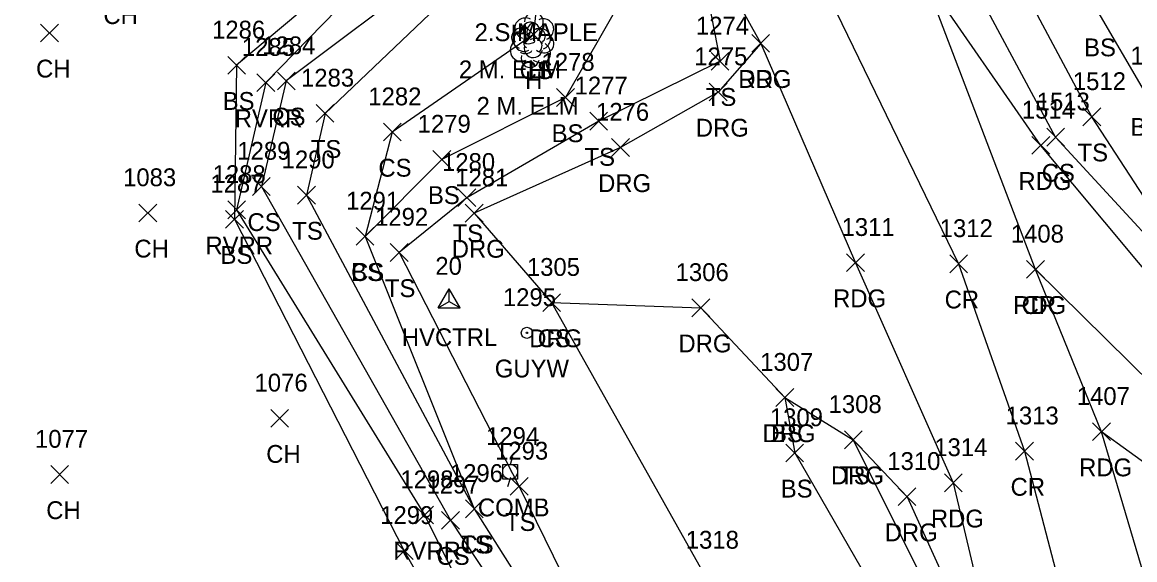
# Model space of a CAD drawing. Extents: x 1469310 to 1475157, y 493997 to 498873.
# Drawn here: x 1469498.4 to 1469623, y 498476.8 to 498537.1 of the extents above; entities that cross this region are included whole.
import ezdxf

# ---------------------------------------------------------------- set-up
doc = ezdxf.new("R2010")
doc.units = 0
for name, color, linetype in [('C_A', 7, 'Continuous'), ('C_I', 7, 'Continuous'), ('CPSM', 7, 'Continuous'), ('L_A', 7, 'Continuous'), ('L_C', 7, 'Continuous'), ('L_I', 7, 'Continuous'), ('L_TIC', 7, 'Continuous'), ('LAWE', 7, 'Continuous'), ('LELB', 7, 'Continuous'), ('LTD', 7, 'Continuous'), ('P_A', 7, 'Continuous'), ('P_I', 7, 'Continuous'), ('P_TIC', 7, 'Continuous'), ('PEU', 7, 'Continuous'), ('PRC', 7, 'Continuous'), ('R_A', 7, 'Continuous'), ('R_I', 7, 'Continuous'), ('R_TIC', 7, 'Continuous'), ('RDG', 7, 'Continuous'), ('U_A', 7, 'Continuous'), ('U_I', 7, 'Continuous'), ('UP', 7, 'Continuous'), ('UPGW', 7, 'Continuous')]:
    doc.layers.add(name, color=color, linetype=linetype)

msp = doc.modelspace()

# ---------------------------------------------------------------- linework, layer by layer
at = {"layer": 'CPSM'}
for p, q in [((1469544.97, 498505), (1469546.22, 498507.16)), ((1469547.47, 498505), (1469546.22, 498507.16)), ((1469546.22, 498505.72), (1469546.22, 498507.16)), ((1469544.97, 498505), (1469546.22, 498505.72)), ((1469544.97, 498505), (1469547.47, 498505)), ((1469546.22, 498505.72), (1469546.22, 498505.72)), ((1469546.22, 498505.72), (1469547.47, 498505))]:
    msp.add_line(p, q, dxfattribs=at)
at = {"layer": 'L_TIC'}
for points in [[(1469500.44, 498534.85), (1469502.44, 498536.85)], [(1469502.44, 498534.85), (1469500.44, 498536.85)], [(1469554.67, 498534.67), (1469556.67, 498536.67)], [(1469556.67, 498534.67), (1469554.67, 498536.67)], [(1469575.57, 498531.67), (1469577.57, 498533.67)], [(1469577.57, 498531.67), (1469575.57, 498533.67)], [(1469521.4, 498531.22), (1469523.4, 498533.22)], [(1469523.4, 498531.22), (1469521.4, 498533.22)], [(1469524.68, 498529.28), (1469526.68, 498531.28)], [(1469526.68, 498529.28), (1469524.68, 498531.28)], [(1469526.97, 498529.46), (1469528.97, 498531.46)], [(1469528.97, 498529.46), (1469526.97, 498531.46)], [(1469558.26, 498527.6), (1469560.26, 498529.6)], [(1469560.26, 498527.6), (1469558.26, 498529.6)], [(1469531.31, 498525.83), (1469533.31, 498527.83)], [(1469533.31, 498525.83), (1469531.31, 498527.83)], [(1469617.23, 498525.44), (1469619.23, 498527.44)], [(1469619.23, 498525.44), (1469617.23, 498527.44)], [(1469561.98, 498524.95), (1469563.98, 498526.95)], [(1469563.98, 498524.95), (1469561.98, 498526.95)], [(1469538.85, 498523.73), (1469540.85, 498525.73)], [(1469540.85, 498523.73), (1469538.85, 498525.73)], [(1469613.18, 498523.16), (1469615.18, 498525.16)], [(1469615.18, 498523.16), (1469613.18, 498525.16)], [(1469544.4, 498520.66), (1469546.4, 498522.66)], [(1469546.4, 498520.66), (1469544.4, 498522.66)], [(1469524.18, 498517.63), (1469526.18, 498519.63)], [(1469526.18, 498517.63), (1469524.18, 498519.63)], [(1469529.23, 498516.66), (1469531.23, 498518.66)], [(1469531.23, 498516.66), (1469529.23, 498518.66)], [(1469547.2, 498516.37), (1469549.2, 498518.37)], [(1469549.2, 498516.37), (1469547.2, 498518.37)], [(1469511.46, 498514.66), (1469513.46, 498516.66)], [(1469513.46, 498514.66), (1469511.46, 498516.66)], [(1469521.16, 498513.95), (1469523.16, 498515.95)], [(1469523.16, 498513.95), (1469521.16, 498515.95)], [(1469521.4, 498515.01), (1469523.4, 498517.01)], [(1469523.4, 498515.01), (1469521.4, 498517.01)], [(1469535.79, 498512.03), (1469537.79, 498514.03)], [(1469537.79, 498512.03), (1469535.79, 498514.03)], [(1469535.79, 498512.03), (1469537.79, 498514.03)], [(1469537.79, 498512.03), (1469535.79, 498514.03)], [(1469539.61, 498510.22), (1469541.61, 498512.22)], [(1469541.61, 498510.22), (1469539.61, 498512.22)], [(1469556.7, 498504.6), (1469558.7, 498506.6)], [(1469558.7, 498504.6), (1469556.7, 498506.6)], [(1469582.84, 498493.95), (1469584.84, 498495.95)], [(1469584.84, 498493.95), (1469582.84, 498495.95)], [(1469526.23, 498491.63), (1469528.23, 498493.63)], [(1469528.23, 498491.63), (1469526.23, 498493.63)], [(1469590.51, 498489.22), (1469592.51, 498491.22)], [(1469592.51, 498489.22), (1469590.51, 498491.22)], [(1469583.94, 498487.74), (1469585.94, 498489.74)], [(1469585.94, 498487.74), (1469583.94, 498489.74)], [(1469501.58, 498485.32), (1469503.58, 498487.32)], [(1469503.58, 498485.32), (1469501.58, 498487.32)], [(1469553.07, 498483.99), (1469555.07, 498485.99)], [(1469555.07, 498483.99), (1469553.07, 498485.99)], [(1469548.04, 498481.48), (1469550.04, 498483.48)], [(1469550.04, 498481.48), (1469548.04, 498483.48)], [(1469548.04, 498481.48), (1469550.04, 498483.48)], [(1469550.04, 498481.48), (1469548.04, 498483.48)], [(1469542.45, 498480.78), (1469544.45, 498482.78)], [(1469544.45, 498480.78), (1469542.45, 498482.78)], [(1469545.36, 498480.19), (1469547.36, 498482.19)], [(1469547.36, 498480.19), (1469545.36, 498482.19)], [(1469540.19, 498476.77), (1469542.19, 498478.77)], [(1469542.19, 498476.77), (1469540.19, 498478.77)]]:
    msp.add_lwpolyline(points, dxfattribs=at)
at = {"layer": 'LAWE'}
msp.add_lwpolyline([(1469541.73, 498555.03), (1469545.19, 498552.67), (1469541.67, 498546.71), (1469525.68, 498530.28), (1469522.4, 498516.01), (1469543.45, 498481.78), (1469558.18, 498452.24), (1469573.2, 498427.49), (1469574.96, 498400.53), (1469574.71, 498375.54), (1469575.48, 498352.31), (1469575.94, 498330.63)], dxfattribs=at)
at = {"layer": 'LELB'}
for points in [[(1469416.82, 498734.31), (1469446.33, 498703.1), (1469470.89, 498677.65), (1469509.28, 498636.71), (1469524.42, 498615.8), (1469544.37, 498592.02), (1469564.88, 498563.16), (1469574.6, 498542.86), (1469576.57, 498532.67), (1469562.98, 498525.95), (1469548.2, 498517.37), (1469540.61, 498511.22), (1469554.07, 498484.99), (1469566.51, 498459.59)], [(1469413.42, 498730.94), (1469442.52, 498698.7), (1469468.45, 498674.77), (1469500.53, 498635.82), (1469519, 498614.53), (1469533.17, 498594.86), (1469544.52, 498587.12), (1469562.89, 498554.7), (1469567.79, 498543.52), (1469559.26, 498528.6), (1469545.4, 498521.66), (1469536.79, 498513.03)], [(1469428.53, 498658.9), (1469433.57, 498648.51), (1469459.29, 498614.44), (1469478.33, 498589.06), (1469483.97, 498576.63), (1469489.34, 498572.76), (1469492.49, 498571.98), (1469507.99, 498581.09), (1469520.42, 498585.29), (1469534.63, 498584.29), (1469538.32, 498574.02), (1469547.83, 498560.42), (1469557.44, 498552.67), (1469555.67, 498535.67), (1469539.85, 498524.73), (1469536.79, 498513.03), (1469549.04, 498482.48), (1469564.46, 498458.05), (1469576.5, 498438.75), (1469578.88, 498431.59)], [(1469540.58, 498559.41), (1469542.48, 498560.06), (1469547.83, 498560.42), (1469552.04, 498551.8), (1469550.24, 498543.93), (1469532.31, 498526.83), (1469530.23, 498517.66), (1469549.04, 498482.48)], [(1469633.1, 498503.6), (1469614.18, 498524.16), (1469603.37, 498544.32), (1469596.34, 498559.71)], [(1469542.74, 498553.27), (1469541.61, 498548.4), (1469522.4, 498532.22), (1469522.16, 498514.95), (1469541.19, 498477.77), (1469556.44, 498450.64), (1469569.24, 498427.49), (1469571.75, 498396.28), (1469571.57, 498374.72), (1469573.65, 498352.84), (1469573.82, 498331.47)], [(1469788.82, 498394.72), (1469772.49, 498406.1), (1469747.63, 498424.65), (1469713.94, 498449.33), (1469681.33, 498467.82), (1469654.97, 498486.97), (1469638.09, 498508.74), (1469624.13, 498529.31), (1469618.93, 498538.23), (1469619.74, 498548.83)], [(1469787.64, 498392.56), (1469771.33, 498404.28), (1469746.15, 498422.39), (1469712.15, 498445.44), (1469680.51, 498465.06), (1469652.75, 498484.35), (1469633.1, 498503.6), (1469618.23, 498526.44), (1469608.67, 498544.39), (1469612.83, 498546.46)], [(1469550.24, 498543.93), (1469544.51, 498542.94), (1469527.97, 498530.46), (1469525.18, 498518.63), (1469546.36, 498481.19), (1469563.05, 498455.92), (1469576.5, 498438.75)], [(1469557.7, 498505.6), (1469574.86, 498475), (1469581.06, 498460.66), (1469589.28, 498449.31), (1469594.14, 498440.51), (1469588.36, 498422.33), (1469583.12, 498414.68)], [(1469583.84, 498494.95), (1469584.94, 498488.74), (1469602.02, 498459.07), (1469610.17, 498437.24), (1469617.9, 498405.01), (1469618.1, 498399.47), (1469619.65, 498362.97), (1469614.57, 498335.86)], [(1469591.51, 498490.22), (1469607.36, 498458.33), (1469613.96, 498438.31), (1469620.12, 498405.06), (1469621.11, 498400.23), (1469624.57, 498362.54), (1469624.83, 498333.54)]]:
    msp.add_lwpolyline(points, dxfattribs=at)
at = {"layer": 'LTD'}
for p, q in [((1469555.3, 498534.56), (1469555.3, 498534.56)), ((1469555.3, 498534.56), (1469555.3, 498534.56)), ((1469555.67, 498535.67), (1469555.67, 498535.67)), ((1469555.67, 498535.67), (1469555.67, 498535.67))]:
    msp.add_line(p, q, dxfattribs=at)
for centre in [(1469555.35, 498536), (1469555.71, 498537.1)]:
    msp.add_arc(centre, 1.05, 335.5272, 180.9563, dxfattribs=at)
for centre, major_axis, ratio, start_param, end_param in [((1469554.88, 498536.33), (1.21, -0.51), 0.895232, 1.570796, 4.712389), ((1469555.46, 498536.12), (-0.208, -0.792), 0.645439, 3.141593, 6.283185), ((1469556.71, 498536.25), (-1.14, -0.48), 0.949671, 1.570796, 4.712389), ((1469554.51, 498535.23), (1.21, -0.51), 0.895232, 1.570796, 4.712389), ((1469554.58, 498534.96), (0.58, -1.04), 0.959034, 3.141593, 6.283185), ((1469555.1, 498535.02), (-0.208, -0.792), 0.645439, 3.141593, 6.283185), ((1469556.17, 498535.5), (-0.5, 0.667), 0.989748, 3.141593, 6.283185), ((1469556.35, 498535.15), (-1.14, -0.48), 0.949671, 1.570796, 4.712389), ((1469556.67, 498534.83), (-1.09, 0.79), 0.841452, 1.570796, 4.712389), ((1469554.22, 498533.85), (0.58, -1.04), 0.959034, 3.141593, 6.283185), ((1469555.21, 498534.92), (-0.625, -0.083), 0.423636, 0, 3.141593), ((1469555.8, 498534.4), (-0.5, 0.667), 0.989748, 3.141593, 6.283185), ((1469556.31, 498533.73), (-1.09, 0.79), 0.841452, 1.570796, 4.712389), ((1469555.31, 498533.06), (0.26, 1.06), 0.942809, 1.570796, 4.712389), ((1469554.85, 498533.81), (-0.625, -0.083), 0.423636, 0, 3.141593), ((1469555.67, 498534.17), (0.26, 1.06), 0.942809, 1.570796, 4.712389)]:
    msp.add_ellipse(centre, major_axis=major_axis, ratio=ratio, start_param=start_param, end_param=end_param, dxfattribs=at)
at = {"layer": 'P_TIC'}
for points in [[(1469580.13, 498533.68), (1469582.13, 498535.68)], [(1469582.13, 498533.68), (1469580.13, 498535.68)], [(1469611.52, 498522.24), (1469613.52, 498524.24)], [(1469613.52, 498522.24), (1469611.52, 498524.24)], [(1469590.75, 498509.08), (1469592.75, 498511.08)], [(1469592.75, 498509.08), (1469590.75, 498511.08)], [(1469602.31, 498508.95), (1469604.31, 498510.95)], [(1469604.31, 498508.95), (1469602.31, 498510.95)], [(1469610.93, 498508.33), (1469612.93, 498510.33)], [(1469612.93, 498508.33), (1469610.93, 498510.33)], [(1469610.93, 498508.33), (1469612.93, 498510.33)], [(1469612.93, 498508.33), (1469610.93, 498510.33)], [(1469618.32, 498490.12), (1469620.32, 498492.12)], [(1469620.32, 498490.12), (1469618.32, 498492.12)], [(1469609.7, 498487.94), (1469611.7, 498489.94)], [(1469611.7, 498487.94), (1469609.7, 498489.94)], [(1469601.71, 498484.38), (1469603.71, 498486.38)], [(1469603.71, 498484.38), (1469601.71, 498486.38)]]:
    msp.add_lwpolyline(points, dxfattribs=at)
at = {"layer": 'PEU'}
for points in [[(1469787.29, 498391.19), (1469770.79, 498403.19), (1469744.94, 498420.51), (1469711.23, 498443.77), (1469680.07, 498463.21), (1469651.58, 498483.41), (1469630.63, 498501.52), (1469612.52, 498523.24), (1469599.41, 498542.19), (1469591.57, 498556.6), (1469575.61, 498583.06), (1469557.31, 498607.49), (1469540.09, 498628.65), (1469536.24, 498634.99), (1469514.98, 498658.51), (1469490.83, 498684.27), (1469472.69, 498702.57), (1469444.89, 498732.16), (1469424.97, 498753.74), (1469411.28, 498767.74), (1469386.83, 498794.07), (1469360.47, 498820.44)], [(1469418.16, 498735.54), (1469447.91, 498704.22), (1469471.83, 498679.03), (1469509.9, 498637.99), (1469529.4, 498614.8), (1469545.14, 498594.13), (1469565.65, 498563.08), (1469576.41, 498543.24), (1469581.13, 498534.68), (1469591.75, 498510.08), (1469602.71, 498485.38), (1469609.03, 498458.44), (1469615.47, 498438.56), (1469621.98, 498404.81), (1469621.72, 498400.42), (1469625.38, 498362.57), (1469626.2, 498333.72)], [(1469637.73, 498433.09), (1469628.78, 498459.19), (1469619.32, 498491.12), (1469611.93, 498509.33), (1469599.41, 498542.19)]]:
    msp.add_lwpolyline(points, dxfattribs=at)
at = {"layer": 'PRC'}
for points in [[(1469423.49, 498741.59), (1469452.57, 498710.45), (1469477.96, 498685.46), (1469512.01, 498647.6), (1469532.7, 498623.32), (1469554.78, 498596.5), (1469570.66, 498571.79), (1469585.25, 498547.18), (1469603.31, 498509.95), (1469610.7, 498488.94), (1469623.7, 498439.14), (1469630.72, 498407.83), (1469631.04, 498401.91), (1469634.46, 498363.9), (1469634.52, 498333.31)], [(1469611.93, 498509.33), (1469635.59, 498485.96), (1469656.26, 498471.44), (1469676.23, 498459.15), (1469677.31, 498457.92), (1469704.76, 498441.38), (1469729.86, 498424.4), (1469757.53, 498405.58), (1469784.33, 498386.63)], [(1469631.71, 498482.13), (1469619.32, 498491.12)]]:
    msp.add_lwpolyline(points, dxfattribs=at)
at = {"layer": 'R_TIC'}
for points in [[(1469580.13, 498533.68), (1469582.13, 498535.68)], [(1469582.13, 498533.68), (1469580.13, 498535.68)], [(1469575.37, 498528.22), (1469577.37, 498530.22)], [(1469577.37, 498528.22), (1469575.37, 498530.22)], [(1469564.42, 498522), (1469566.42, 498524)], [(1469566.42, 498522), (1469564.42, 498524)], [(1469548.02, 498514.64), (1469550.02, 498516.64)], [(1469550.02, 498514.64), (1469548.02, 498516.64)], [(1469556.7, 498504.6), (1469558.7, 498506.6)], [(1469558.7, 498504.6), (1469556.7, 498506.6)], [(1469573.42, 498504.02), (1469575.42, 498506.02)], [(1469575.42, 498504.02), (1469573.42, 498506.02)], [(1469582.84, 498493.95), (1469584.84, 498495.95)], [(1469584.84, 498493.95), (1469582.84, 498495.95)], [(1469590.51, 498489.22), (1469592.51, 498491.22)], [(1469592.51, 498489.22), (1469590.51, 498491.22)], [(1469596.53, 498482.83), (1469598.53, 498484.83)], [(1469598.53, 498482.83), (1469596.53, 498484.83)]]:
    msp.add_lwpolyline(points, dxfattribs=at)
at = {"layer": 'RDG'}
msp.add_lwpolyline([(1469581.13, 498534.68), (1469576.37, 498529.22), (1469565.42, 498523), (1469549.02, 498515.64), (1469557.7, 498505.6), (1469574.42, 498505.02), (1469583.84, 498494.95), (1469591.51, 498490.22), (1469597.53, 498483.83), (1469609.03, 498458.44)], dxfattribs=at)
at = {"layer": 'UP'}
for p, q in [((1469552.22, 498485.8), (1469552.22, 498487.46)), ((1469552.22, 498487.46), (1469553.88, 498487.46)), ((1469553.3, 498488.3), (1469553.05, 498487.46)), ((1469553.88, 498487.46), (1469553.88, 498485.8)), ((1469553.05, 498486.63), (1469553.05, 498486.63)), ((1469553.88, 498485.8), (1469552.22, 498485.8)), ((1469552.8, 498484.96), (1469553.05, 498485.8))]:
    msp.add_line(p, q, dxfattribs=at)
msp.add_circle((1469553.05, 498486.63), 0.833, dxfattribs=at)
at = {"layer": 'UPGW'}
for radius in [0.625, 0.0833]:
    msp.add_circle((1469554.93, 498502.21), radius, dxfattribs=at)

# ---------------------------------------------------------------- texts
at = {"layer": 'C_A'}
msp.add_text('HVCTRL', height=2, dxfattribs=at).set_placement((1469540.91, 498500.72))
at = {"layer": 'C_I'}
msp.add_text('20', height=2, dxfattribs=at).set_placement((1469544.67, 498508.72))
at = {"layer": 'L_A'}
for s, p in [('CH', (1469507.47, 498536.85)), ('H', (1469553.12, 498534.76)), ('BS', (1469617.37, 498533.23)), ('CH', (1469499.93, 498530.85)), ('CS', (1469554.11, 498530.67)), ('H', (1469555.1, 498530.67)), ('H', (1469554.74, 498529.56)), ('TS', (1469574.98, 498527.67)), ('BS', (1469520.84, 498527.22)), ('RVRR', (1469522.19, 498525.28)), ('CS', (1469526.41, 498525.46)), ('BS', (1469622.57, 498524.31)), ('BS', (1469557.7, 498523.6)), ('TS', (1469530.72, 498521.83)), ('TS', (1469616.64, 498521.44)), ('TS', (1469561.39, 498520.95)), ('CS', (1469538.29, 498519.73)), ('CS', (1469612.62, 498519.16)), ('BS', (1469543.84, 498516.66)), ('CS', (1469523.62, 498513.63)), ('TS', (1469528.64, 498512.66)), ('TS', (1469546.61, 498512.37)), ('CH', (1469510.94, 498510.66)), ('RVRR', (1469518.91, 498511.01)), ('BS', (1469520.6, 498509.95)), ('CS', (1469535.23, 498508.03)), ('BS', (1469535.23, 498508.03)), ('TS', (1469539.02, 498506.22)), ('CS', (1469556.14, 498500.6)), ('BS', (1469582.28, 498489.95)), ('CH', (1469525.72, 498487.63)), ('TS', (1469589.92, 498485.22)), ('BS', (1469583.38, 498483.74)), ('CH', (1469501.07, 498481.32)), ('TS', (1469552.48, 498479.99)), ('RVRR', (1469539.96, 498476.78)), ('TS', (1469547.45, 498477.48)), ('CS', (1469547.49, 498477.48)), ('CS', (1469544.8, 498476.19))]:
    msp.add_text(s, height=2, dxfattribs=at).set_placement(p)
at = {"layer": 'L_C'}
for s, p in [('2.S.MAPLE', (1469549.07, 498534.93)), ('2 M. ELM', (1469547.31, 498530.76)), ('2 M. ELM', (1469549.29, 498526.67))]:
    msp.add_text(s, height=2, dxfattribs=at).set_placement(p)
at = {"layer": 'L_I'}
for s, p in [('1286', (1469519.65, 498535.22)), ('1274', (1469573.87, 498535.67)), ('1285', (1469522.99, 498533.28)), ('1284', (1469525.27, 498533.46)), ('1278', (1469556.57, 498531.6)), ('1511', (1469622.57, 498532.31)), ('1283', (1469529.62, 498529.83)), ('1277', (1469560.28, 498528.95)), ('1512', (1469616.11, 498529.44)), ('1282', (1469537.16, 498527.73)), ('1513', (1469612.06, 498527.16)), ('1279', (1469542.69, 498524.66)), ('1289', (1469522.48, 498521.63)), ('1290', (1469527.45, 498520.66)), ('1280', (1469545.42, 498520.37)), ('1288', (1469519.71, 498519.01)), ('1083', (1469509.68, 498518.66)), ('1287', (1469519.46, 498517.95)), ('1291', (1469534.67, 498516.03)), ('1291', (1469534.67, 498516.03)), ('1292', (1469537.92, 498514.22)), ('1305', (1469554.93, 498508.6)), ('1307', (1469581.07, 498497.95)), ('1076', (1469524.41, 498495.63)), ('1308', (1469588.74, 498493.22)), ('1309', (1469582.16, 498491.74)), ('1077', (1469499.81, 498489.32)), ('1293', (1469551.37, 498487.99)), ('1296', (1469546.3, 498485.48)), ('1296', (1469546.3, 498485.48)), ('1298', (1469540.76, 498484.78)), ('1297', (1469543.67, 498484.19)), ('1299', (1469538.49, 498480.77)), ('1318', (1469572.74, 498478))]:
    msp.add_text(s, height=2, dxfattribs=at).set_placement(p)
at = {"layer": 'P_A'}
for s, p in [('RDG', (1469578.62, 498529.68)), ('RDG', (1469610.01, 498518.24)), ('RDG', (1469589.24, 498505.08)), ('CR', (1469601.74, 498504.95)), ('RDG', (1469609.42, 498504.33)), ('CR', (1469610.37, 498504.33)), ('RDG', (1469616.81, 498486.12)), ('CR', (1469609.13, 498483.94)), ('RDG', (1469600.2, 498480.38))]:
    msp.add_text(s, height=2, dxfattribs=at).set_placement(p)
at = {"layer": 'P_I'}
for s, p in [('1514', (1469610.39, 498526.24)), ('1311', (1469590.19, 498513.08)), ('1312', (1469601.19, 498512.95)), ('1408', (1469609.16, 498512.33)), ('1408', (1469609.16, 498512.33)), ('1407', (1469616.55, 498494.12)), ('1313', (1469608.58, 498491.94)), ('1314', (1469600.58, 498488.38))]:
    msp.add_text(s, height=2, dxfattribs=at).set_placement(p)
at = {"layer": 'R_A'}
for p in [(1469578.62, 498529.68), (1469573.86, 498524.22), (1469562.91, 498518), (1469546.51, 498510.64), (1469555.19, 498500.6), (1469571.91, 498500.02), (1469581.33, 498489.95), (1469589, 498485.22), (1469595.02, 498478.83)]:
    msp.add_text('DRG', height=2, dxfattribs=at).set_placement(p)
at = {"layer": 'R_I'}
for s, p in [('1275', (1469573.68, 498532.22)), ('1276', (1469562.68, 498526)), ('1281', (1469546.9, 498518.64)), ('1305', (1469554.93, 498508.6)), ('1306', (1469571.6, 498508.02)), ('1307', (1469581.07, 498497.95)), ('1308', (1469588.74, 498493.22)), ('1310', (1469595.32, 498486.83))]:
    msp.add_text(s, height=2, dxfattribs=at).set_placement(p)
at = {"layer": 'U_A'}
for s, p in [('GUYW', (1469551.33, 498497.21)), ('COMB', (1469549.44, 498481.63))]:
    msp.add_text(s, height=2, dxfattribs=at).set_placement(p)
at = {"layer": 'U_I'}
for s, p in [('1295', (1469552.24, 498505.21)), ('1294', (1469550.36, 498489.63))]:
    msp.add_text(s, height=2, dxfattribs=at).set_placement(p)

doc.saveas('drawing.dxf')
